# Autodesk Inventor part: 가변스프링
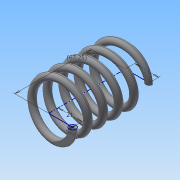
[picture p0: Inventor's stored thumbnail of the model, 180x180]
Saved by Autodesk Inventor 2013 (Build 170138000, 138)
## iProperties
Created: 2019-10
Part Number: 가변스프링
Material: 일반
Document SubType Name: Modeling
Designer: Administrator
Density: 1 g/cm^3
Mass: 18.3003 g
Surface Area: 124.153 cm^2
Volume: 18.3003 cm^3
Author: Administrator
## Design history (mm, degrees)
sketch "스케치1"
  geometry: L1 (0, 0)-(0, 67.25); L2 (0, 0)-(21, 0); L3 (0, 67.25)-(21, 67.25); C1 r 3 at (21, 0)
  constraints: 6 end point, 2 horizontal, 1 centre point, 1 coincident, 1 vertical
  dimensions: "d2" = 67.25 distance of L1.start L1.end (derived); "d3" = 21 distance of L1.start L2.end; "d4" = 6 diameter of C1; "d5" = 21 distance of L1.end L3.end
feature "코일1" pitch "d6" = 10; turns "d8" = 5; dims "d7" = 67.25 (= d2), "d9" = 0, angle "d10" = 90 deg, angle "d11" = 90 deg, "d12" = 0, "d13" = 0
sketch "스케치2"
  geometry: L1 (-37.447, 67.25)-(37.447, 67.25); L2 (37.447, 67.25)-(37.447, 0); L3 (37.447, 0)-(-37.447, 0); L4 (-37.447, 0)-(-37.447, 67.25); 2 further points
  constraints: 8 end point, 2 parallel, 1 coincident, 1 horizontal, 1 midpoint, 1 perpendicular
  dimensions: "d14" = 67.25 distance between parallel lines of L3 L1 (= d2)
extrude "돌출1" sketch "스케치2" stored distance "d17" = 0; taper "d18" = 0 deg
node "솔리드1"
